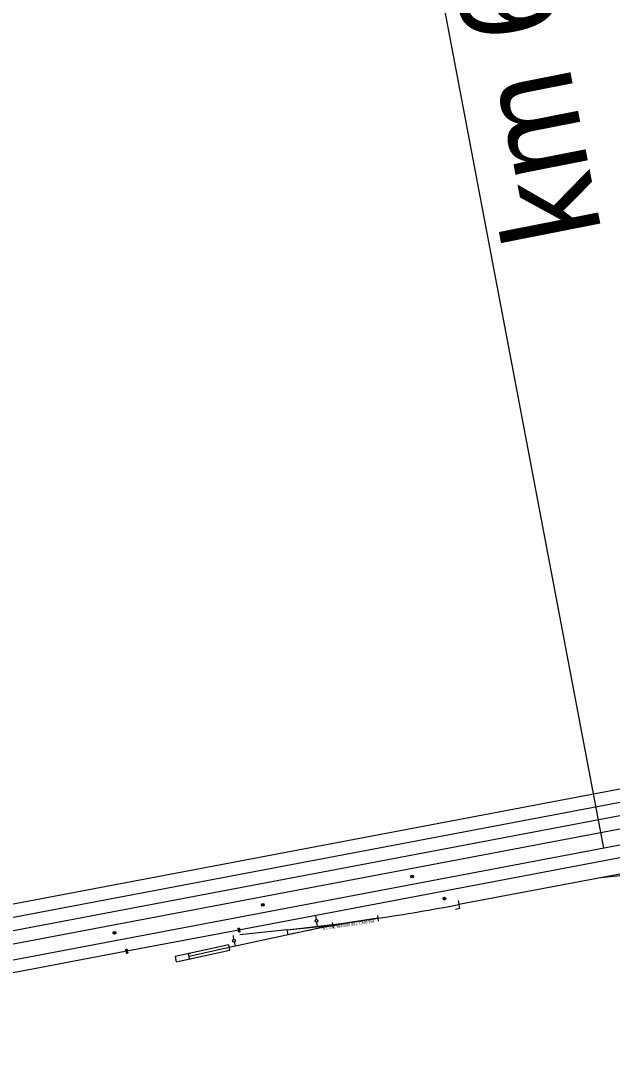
# Model space of a CAD drawing. Extents: x 6540402 to 6566579, y 5525343 to 5532423.
# Drawn here: x 6557411.7 to 6557627, y 5528631.9 to 5529013.3 of the extents above; entities that cross this region are included whole.
import ezdxf

# ---------------------------------------------------------------- set-up
doc = ezdxf.new("R2010")
doc.units = 0
for name, color, linetype in [('IR_ps_geometria', 7, 'Continuous'), ('T_plan_koziol oporowy', 7, 'Continuous'), ('TOR_PS_ODW-studnie betonowe', 7, 'Continuous'), ('TOR_PS_OPIS_T-opisy dodatkowe', 7, 'Continuous'), ('TOR_PS_OPIS_T-symbole geometrii', 7, 'Continuous'), ('TOR_PS_OPIS_T-ukresy', 7, 'Continuous'), ('TOR_PS_T-rozjazdy projektowane', 7, 'Continuous'), ('TOR_PS_T-tory projektowane', 7, 'Continuous')]:
    doc.layers.add(name, color=color, linetype=linetype)

# ---------------------------------------------------------------- blocks, each defined once
blk = doc.blocks.new('koziol 15+5')
at = {"layer": 'T_plan_koziol oporowy'}
for p, q in [((15, 1), (14.3, 1)), ((15, 1), (15, -1)), ((20, 0), (20, 1)), ((0, 0), (15, 0)), ((15, -1), (14.3, -1))]:
    blk.add_line(p, q, dxfattribs=at)
blk.add_lwpolyline([(20, 1), (0, 1), (0, -1), (20, -1)], close=True, dxfattribs=at)

msp = doc.modelspace()

# ---------------------------------------------------------------- linework, layer by layer
at = {"layer": 'IR_ps_geometria'}
for points in [[(6557491.12, 5528682.16), (6557491.16, 5528681.91), (6557491.2, 5528681.92), (6557491.23, 5528681.92), (6557491.26, 5528681.91), (6557491.29, 5528681.9), (6557491.32, 5528681.89), (6557491.35, 5528681.88), (6557491.38, 5528681.85), (6557491.4, 5528681.83), (6557491.42, 5528681.81), (6557491.44, 5528681.78), (6557491.45, 5528681.75), (6557491.46, 5528681.71), (6557491.46, 5528681.68), (6557491.46, 5528681.65), (6557491.46, 5528681.62), (6557491.45, 5528681.59), (6557491.43, 5528681.56), (6557491.42, 5528681.53), (6557491.4, 5528681.5), (6557491.37, 5528681.48), (6557491.35, 5528681.46), (6557491.32, 5528681.44), (6557491.29, 5528681.43), (6557491.26, 5528681.42), (6557491.22, 5528681.42), (6557491.19, 5528681.42), (6557491.16, 5528681.42), (6557491.13, 5528681.43), (6557491.1, 5528681.45), (6557491.07, 5528681.46), (6557491.04, 5528681.48), (6557491.02, 5528681.51), (6557491, 5528681.53), (6557490.99, 5528681.56), (6557490.97, 5528681.59), (6557490.96, 5528681.62), (6557490.96, 5528681.65), (6557490.96, 5528681.69), (6557490.97, 5528681.72), (6557490.97, 5528681.75), (6557490.99, 5528681.78), (6557491, 5528681.81), (6557491.02, 5528681.83), (6557491.05, 5528681.86), (6557491.07, 5528681.88), (6557491.1, 5528681.89), (6557491.13, 5528681.91), (6557491.16, 5528681.91), (6557491.07, 5528682.41), (6557491.04, 5528682.4), (6557491.01, 5528682.4), (6557490.97, 5528682.41), (6557490.94, 5528682.41), (6557490.91, 5528682.43), (6557490.88, 5528682.44), (6557490.86, 5528682.46), (6557490.83, 5528682.49), (6557490.81, 5528682.51), (6557490.8, 5528682.54), (6557490.79, 5528682.57), (6557490.78, 5528682.6), (6557490.77, 5528682.64), (6557490.77, 5528682.67), (6557490.78, 5528682.7), (6557490.79, 5528682.73), (6557490.8, 5528682.76), (6557490.82, 5528682.79), (6557490.84, 5528682.82), (6557490.86, 5528682.84), (6557490.89, 5528682.86), (6557490.92, 5528682.88), (6557490.95, 5528682.89), (6557490.98, 5528682.9), (6557491.01, 5528682.9), (6557491.04, 5528682.9), (6557491.08, 5528682.9), (6557491.11, 5528682.89), (6557491.14, 5528682.87), (6557491.16, 5528682.86), (6557491.19, 5528682.84), (6557491.21, 5528682.81), (6557491.23, 5528682.79), (6557491.25, 5528682.76), (6557491.26, 5528682.73), (6557491.27, 5528682.7), (6557491.27, 5528682.67), (6557491.27, 5528682.63), (6557491.27, 5528682.6), (6557491.26, 5528682.57), (6557491.25, 5528682.54), (6557491.23, 5528682.51), (6557491.21, 5528682.48), (6557491.19, 5528682.46), (6557491.16, 5528682.44), (6557491.13, 5528682.43), (6557491.1, 5528682.41), (6557491.07, 5528682.41)], [(6557491.12, 5528682.16), (6557491.16, 5528681.91), (6557491.2, 5528681.92), (6557491.23, 5528681.92), (6557491.26, 5528681.91), (6557491.29, 5528681.9), (6557491.32, 5528681.89), (6557491.35, 5528681.88), (6557491.38, 5528681.85), (6557491.4, 5528681.83), (6557491.42, 5528681.81), (6557491.44, 5528681.78), (6557491.45, 5528681.75), (6557491.46, 5528681.71), (6557491.46, 5528681.68), (6557491.46, 5528681.65), (6557491.46, 5528681.62), (6557491.45, 5528681.59), (6557491.43, 5528681.56), (6557491.42, 5528681.53), (6557491.4, 5528681.5), (6557491.37, 5528681.48), (6557491.35, 5528681.46), (6557491.32, 5528681.44), (6557491.29, 5528681.43), (6557491.26, 5528681.42), (6557491.22, 5528681.42), (6557491.19, 5528681.42), (6557491.16, 5528681.42), (6557491.13, 5528681.43), (6557491.1, 5528681.45), (6557491.07, 5528681.46), (6557491.04, 5528681.48), (6557491.02, 5528681.51), (6557491, 5528681.53), (6557490.99, 5528681.56), (6557490.97, 5528681.59), (6557490.96, 5528681.62), (6557490.96, 5528681.65), (6557490.96, 5528681.69), (6557490.97, 5528681.72), (6557490.97, 5528681.75), (6557490.99, 5528681.78), (6557491, 5528681.81), (6557491.02, 5528681.83), (6557491.05, 5528681.86), (6557491.07, 5528681.88), (6557491.1, 5528681.89), (6557491.13, 5528681.91), (6557491.16, 5528681.91), (6557491.07, 5528682.41), (6557491.04, 5528682.4), (6557491.01, 5528682.4), (6557490.97, 5528682.41), (6557490.94, 5528682.41), (6557490.91, 5528682.43), (6557490.88, 5528682.44), (6557490.86, 5528682.46), (6557490.83, 5528682.49), (6557490.81, 5528682.51), (6557490.8, 5528682.54), (6557490.79, 5528682.57), (6557490.78, 5528682.6), (6557490.77, 5528682.64), (6557490.77, 5528682.67), (6557490.78, 5528682.7), (6557490.79, 5528682.73), (6557490.8, 5528682.76), (6557490.82, 5528682.79), (6557490.84, 5528682.82), (6557490.86, 5528682.84), (6557490.89, 5528682.86), (6557490.92, 5528682.88), (6557490.95, 5528682.89), (6557490.98, 5528682.9), (6557491.01, 5528682.9), (6557491.04, 5528682.9), (6557491.08, 5528682.9), (6557491.11, 5528682.89), (6557491.14, 5528682.87), (6557491.16, 5528682.86), (6557491.19, 5528682.84), (6557491.21, 5528682.81), (6557491.23, 5528682.79), (6557491.25, 5528682.76), (6557491.26, 5528682.73), (6557491.27, 5528682.7), (6557491.27, 5528682.67), (6557491.27, 5528682.63), (6557491.27, 5528682.6), (6557491.26, 5528682.57), (6557491.25, 5528682.54), (6557491.23, 5528682.51), (6557491.21, 5528682.48), (6557491.19, 5528682.46), (6557491.16, 5528682.44), (6557491.13, 5528682.43), (6557491.1, 5528682.41), (6557491.07, 5528682.41)], [(6557491.12, 5528682.16), (6557491.16, 5528681.91), (6557491.2, 5528681.92), (6557491.23, 5528681.92), (6557491.26, 5528681.91), (6557491.29, 5528681.9), (6557491.32, 5528681.89), (6557491.35, 5528681.88), (6557491.38, 5528681.85), (6557491.4, 5528681.83), (6557491.42, 5528681.81), (6557491.44, 5528681.78), (6557491.45, 5528681.75), (6557491.46, 5528681.71), (6557491.46, 5528681.68), (6557491.46, 5528681.65), (6557491.46, 5528681.62), (6557491.45, 5528681.59), (6557491.43, 5528681.56), (6557491.42, 5528681.53), (6557491.4, 5528681.5), (6557491.37, 5528681.48), (6557491.35, 5528681.46), (6557491.32, 5528681.44), (6557491.29, 5528681.43), (6557491.26, 5528681.42), (6557491.22, 5528681.42), (6557491.19, 5528681.42), (6557491.16, 5528681.42), (6557491.13, 5528681.43), (6557491.1, 5528681.45), (6557491.07, 5528681.46), (6557491.04, 5528681.48), (6557491.02, 5528681.51), (6557491, 5528681.53), (6557490.99, 5528681.56), (6557490.97, 5528681.59), (6557490.96, 5528681.62), (6557490.96, 5528681.65), (6557490.96, 5528681.69), (6557490.97, 5528681.72), (6557490.97, 5528681.75), (6557490.99, 5528681.78), (6557491, 5528681.81), (6557491.02, 5528681.83), (6557491.05, 5528681.86), (6557491.07, 5528681.88), (6557491.1, 5528681.89), (6557491.13, 5528681.91), (6557491.16, 5528681.91), (6557491.07, 5528682.41), (6557491.04, 5528682.4), (6557491.01, 5528682.4), (6557490.97, 5528682.41), (6557490.94, 5528682.41), (6557490.91, 5528682.43), (6557490.88, 5528682.44), (6557490.86, 5528682.46), (6557490.83, 5528682.49), (6557490.81, 5528682.51), (6557490.8, 5528682.54), (6557490.79, 5528682.57), (6557490.78, 5528682.6), (6557490.77, 5528682.64), (6557490.77, 5528682.67), (6557490.78, 5528682.7), (6557490.79, 5528682.73), (6557490.8, 5528682.76), (6557490.82, 5528682.79), (6557490.84, 5528682.82), (6557490.86, 5528682.84), (6557490.89, 5528682.86), (6557490.92, 5528682.88), (6557490.95, 5528682.89), (6557490.98, 5528682.9), (6557491.01, 5528682.9), (6557491.04, 5528682.9), (6557491.08, 5528682.9), (6557491.11, 5528682.89), (6557491.14, 5528682.87), (6557491.16, 5528682.86), (6557491.19, 5528682.84), (6557491.21, 5528682.81), (6557491.23, 5528682.79), (6557491.25, 5528682.76), (6557491.26, 5528682.73), (6557491.27, 5528682.7), (6557491.27, 5528682.67), (6557491.27, 5528682.63), (6557491.27, 5528682.6), (6557491.26, 5528682.57), (6557491.25, 5528682.54), (6557491.23, 5528682.51), (6557491.21, 5528682.48), (6557491.19, 5528682.46), (6557491.16, 5528682.44), (6557491.13, 5528682.43), (6557491.1, 5528682.41), (6557491.07, 5528682.41)], [(6557491.12, 5528682.16), (6557491.16, 5528681.91), (6557491.2, 5528681.92), (6557491.23, 5528681.92), (6557491.26, 5528681.91), (6557491.29, 5528681.9), (6557491.32, 5528681.89), (6557491.35, 5528681.88), (6557491.38, 5528681.85), (6557491.4, 5528681.83), (6557491.42, 5528681.81), (6557491.44, 5528681.78), (6557491.45, 5528681.75), (6557491.46, 5528681.71), (6557491.46, 5528681.68), (6557491.46, 5528681.65), (6557491.46, 5528681.62), (6557491.45, 5528681.59), (6557491.43, 5528681.56), (6557491.42, 5528681.53), (6557491.4, 5528681.5), (6557491.37, 5528681.48), (6557491.35, 5528681.46), (6557491.32, 5528681.44), (6557491.29, 5528681.43), (6557491.26, 5528681.42), (6557491.22, 5528681.42), (6557491.19, 5528681.42), (6557491.16, 5528681.42), (6557491.13, 5528681.43), (6557491.1, 5528681.45), (6557491.07, 5528681.46), (6557491.04, 5528681.48), (6557491.02, 5528681.51), (6557491, 5528681.53), (6557490.99, 5528681.56), (6557490.97, 5528681.59), (6557490.96, 5528681.62), (6557490.96, 5528681.65), (6557490.96, 5528681.69), (6557490.97, 5528681.72), (6557490.97, 5528681.75), (6557490.99, 5528681.78), (6557491, 5528681.81), (6557491.02, 5528681.83), (6557491.05, 5528681.86), (6557491.07, 5528681.88), (6557491.1, 5528681.89), (6557491.13, 5528681.91), (6557491.16, 5528681.91), (6557491.07, 5528682.41), (6557491.04, 5528682.4), (6557491.01, 5528682.4), (6557490.97, 5528682.41), (6557490.94, 5528682.41), (6557490.91, 5528682.43), (6557490.88, 5528682.44), (6557490.86, 5528682.46), (6557490.83, 5528682.49), (6557490.81, 5528682.51), (6557490.8, 5528682.54), (6557490.79, 5528682.57), (6557490.78, 5528682.6), (6557490.77, 5528682.64), (6557490.77, 5528682.67), (6557490.78, 5528682.7), (6557490.79, 5528682.73), (6557490.8, 5528682.76), (6557490.82, 5528682.79), (6557490.84, 5528682.82), (6557490.86, 5528682.84), (6557490.89, 5528682.86), (6557490.92, 5528682.88), (6557490.95, 5528682.89), (6557490.98, 5528682.9), (6557491.01, 5528682.9), (6557491.04, 5528682.9), (6557491.08, 5528682.9), (6557491.11, 5528682.89), (6557491.14, 5528682.87), (6557491.16, 5528682.86), (6557491.19, 5528682.84), (6557491.21, 5528682.81), (6557491.23, 5528682.79), (6557491.25, 5528682.76), (6557491.26, 5528682.73), (6557491.27, 5528682.7), (6557491.27, 5528682.67), (6557491.27, 5528682.63), (6557491.27, 5528682.6), (6557491.26, 5528682.57), (6557491.25, 5528682.54), (6557491.23, 5528682.51), (6557491.21, 5528682.48), (6557491.19, 5528682.46), (6557491.16, 5528682.44), (6557491.13, 5528682.43), (6557491.1, 5528682.41), (6557491.07, 5528682.41)], [(6557450.25, 5528674.41), (6557450.3, 5528674.17), (6557450.33, 5528674.17), (6557450.36, 5528674.17), (6557450.39, 5528674.17), (6557450.43, 5528674.16), (6557450.46, 5528674.15), (6557450.48, 5528674.13), (6557450.51, 5528674.11), (6557450.53, 5528674.09), (6557450.55, 5528674.06), (6557450.57, 5528674.03), (6557450.58, 5528674), (6557450.59, 5528673.97), (6557450.59, 5528673.94), (6557450.59, 5528673.9), (6557450.59, 5528673.87), (6557450.58, 5528673.84), (6557450.57, 5528673.81), (6557450.55, 5528673.78), (6557450.53, 5528673.76), (6557450.51, 5528673.73), (6557450.48, 5528673.71), (6557450.45, 5528673.7), (6557450.42, 5528673.68), (6557450.39, 5528673.68), (6557450.36, 5528673.67), (6557450.32, 5528673.67), (6557450.29, 5528673.68), (6557450.26, 5528673.69), (6557450.23, 5528673.7), (6557450.2, 5528673.72), (6557450.18, 5528673.74), (6557450.15, 5528673.76), (6557450.13, 5528673.78), (6557450.12, 5528673.81), (6557450.11, 5528673.84), (6557450.1, 5528673.88), (6557450.09, 5528673.91), (6557450.09, 5528673.94), (6557450.1, 5528673.97), (6557450.11, 5528674), (6557450.12, 5528674.03), (6557450.14, 5528674.06), (6557450.16, 5528674.09), (6557450.18, 5528674.11), (6557450.21, 5528674.13), (6557450.23, 5528674.15), (6557450.27, 5528674.16), (6557450.3, 5528674.17), (6557450.2, 5528674.66), (6557450.17, 5528674.65), (6557450.14, 5528674.66), (6557450.11, 5528674.66), (6557450.07, 5528674.67), (6557450.04, 5528674.68), (6557450.02, 5528674.7), (6557449.99, 5528674.72), (6557449.97, 5528674.74), (6557449.95, 5528674.77), (6557449.93, 5528674.8), (6557449.92, 5528674.83), (6557449.91, 5528674.86), (6557449.91, 5528674.89), (6557449.91, 5528674.92), (6557449.91, 5528674.96), (6557449.92, 5528674.99), (6557449.93, 5528675.02), (6557449.95, 5528675.05), (6557449.97, 5528675.07), (6557449.99, 5528675.09), (6557450.02, 5528675.11), (6557450.05, 5528675.13), (6557450.08, 5528675.14), (6557450.11, 5528675.15), (6557450.14, 5528675.15), (6557450.18, 5528675.15), (6557450.21, 5528675.15), (6557450.24, 5528675.14), (6557450.27, 5528675.13), (6557450.3, 5528675.11), (6557450.32, 5528675.09), (6557450.35, 5528675.07), (6557450.37, 5528675.04), (6557450.38, 5528675.01), (6557450.39, 5528674.98), (6557450.4, 5528674.95), (6557450.41, 5528674.92), (6557450.41, 5528674.89), (6557450.4, 5528674.85), (6557450.39, 5528674.82), (6557450.38, 5528674.79), (6557450.36, 5528674.76), (6557450.34, 5528674.74), (6557450.32, 5528674.72), (6557450.29, 5528674.7), (6557450.27, 5528674.68), (6557450.24, 5528674.67), (6557450.2, 5528674.66)], [(6557450.25, 5528674.41), (6557450.3, 5528674.17), (6557450.33, 5528674.17), (6557450.36, 5528674.17), (6557450.39, 5528674.17), (6557450.43, 5528674.16), (6557450.46, 5528674.15), (6557450.48, 5528674.13), (6557450.51, 5528674.11), (6557450.53, 5528674.09), (6557450.55, 5528674.06), (6557450.57, 5528674.03), (6557450.58, 5528674), (6557450.59, 5528673.97), (6557450.59, 5528673.94), (6557450.59, 5528673.9), (6557450.59, 5528673.87), (6557450.58, 5528673.84), (6557450.57, 5528673.81), (6557450.55, 5528673.78), (6557450.53, 5528673.76), (6557450.51, 5528673.73), (6557450.48, 5528673.71), (6557450.45, 5528673.7), (6557450.42, 5528673.68), (6557450.39, 5528673.68), (6557450.36, 5528673.67), (6557450.32, 5528673.67), (6557450.29, 5528673.68), (6557450.26, 5528673.69), (6557450.23, 5528673.7), (6557450.2, 5528673.72), (6557450.18, 5528673.74), (6557450.15, 5528673.76), (6557450.13, 5528673.78), (6557450.12, 5528673.81), (6557450.11, 5528673.84), (6557450.1, 5528673.88), (6557450.09, 5528673.91), (6557450.09, 5528673.94), (6557450.1, 5528673.97), (6557450.11, 5528674), (6557450.12, 5528674.03), (6557450.14, 5528674.06), (6557450.16, 5528674.09), (6557450.18, 5528674.11), (6557450.21, 5528674.13), (6557450.23, 5528674.15), (6557450.27, 5528674.16), (6557450.3, 5528674.17), (6557450.2, 5528674.66), (6557450.17, 5528674.65), (6557450.14, 5528674.66), (6557450.11, 5528674.66), (6557450.07, 5528674.67), (6557450.04, 5528674.68), (6557450.02, 5528674.7), (6557449.99, 5528674.72), (6557449.97, 5528674.74), (6557449.95, 5528674.77), (6557449.93, 5528674.8), (6557449.92, 5528674.83), (6557449.91, 5528674.86), (6557449.91, 5528674.89), (6557449.91, 5528674.92), (6557449.91, 5528674.96), (6557449.92, 5528674.99), (6557449.93, 5528675.02), (6557449.95, 5528675.05), (6557449.97, 5528675.07), (6557449.99, 5528675.09), (6557450.02, 5528675.11), (6557450.05, 5528675.13), (6557450.08, 5528675.14), (6557450.11, 5528675.15), (6557450.14, 5528675.15), (6557450.18, 5528675.15), (6557450.21, 5528675.15), (6557450.24, 5528675.14), (6557450.27, 5528675.13), (6557450.3, 5528675.11), (6557450.32, 5528675.09), (6557450.35, 5528675.07), (6557450.37, 5528675.04), (6557450.38, 5528675.01), (6557450.39, 5528674.98), (6557450.4, 5528674.95), (6557450.41, 5528674.92), (6557450.41, 5528674.89), (6557450.4, 5528674.85), (6557450.39, 5528674.82), (6557450.38, 5528674.79), (6557450.36, 5528674.76), (6557450.34, 5528674.74), (6557450.32, 5528674.72), (6557450.29, 5528674.7), (6557450.27, 5528674.68), (6557450.24, 5528674.67), (6557450.2, 5528674.66)], [(6557450.25, 5528674.41), (6557450.3, 5528674.17), (6557450.33, 5528674.17), (6557450.36, 5528674.17), (6557450.39, 5528674.17), (6557450.43, 5528674.16), (6557450.46, 5528674.15), (6557450.48, 5528674.13), (6557450.51, 5528674.11), (6557450.53, 5528674.09), (6557450.55, 5528674.06), (6557450.57, 5528674.03), (6557450.58, 5528674), (6557450.59, 5528673.97), (6557450.59, 5528673.94), (6557450.59, 5528673.9), (6557450.59, 5528673.87), (6557450.58, 5528673.84), (6557450.57, 5528673.81), (6557450.55, 5528673.78), (6557450.53, 5528673.76), (6557450.51, 5528673.73), (6557450.48, 5528673.71), (6557450.45, 5528673.7), (6557450.42, 5528673.68), (6557450.39, 5528673.68), (6557450.36, 5528673.67), (6557450.32, 5528673.67), (6557450.29, 5528673.68), (6557450.26, 5528673.69), (6557450.23, 5528673.7), (6557450.2, 5528673.72), (6557450.18, 5528673.74), (6557450.15, 5528673.76), (6557450.13, 5528673.78), (6557450.12, 5528673.81), (6557450.11, 5528673.84), (6557450.1, 5528673.88), (6557450.09, 5528673.91), (6557450.09, 5528673.94), (6557450.1, 5528673.97), (6557450.11, 5528674), (6557450.12, 5528674.03), (6557450.14, 5528674.06), (6557450.16, 5528674.09), (6557450.18, 5528674.11), (6557450.21, 5528674.13), (6557450.23, 5528674.15), (6557450.27, 5528674.16), (6557450.3, 5528674.17), (6557450.2, 5528674.66), (6557450.17, 5528674.65), (6557450.14, 5528674.66), (6557450.11, 5528674.66), (6557450.07, 5528674.67), (6557450.04, 5528674.68), (6557450.02, 5528674.7), (6557449.99, 5528674.72), (6557449.97, 5528674.74), (6557449.95, 5528674.77), (6557449.93, 5528674.8), (6557449.92, 5528674.83), (6557449.91, 5528674.86), (6557449.91, 5528674.89), (6557449.91, 5528674.92), (6557449.91, 5528674.96), (6557449.92, 5528674.99), (6557449.93, 5528675.02), (6557449.95, 5528675.05), (6557449.97, 5528675.07), (6557449.99, 5528675.09), (6557450.02, 5528675.11), (6557450.05, 5528675.13), (6557450.08, 5528675.14), (6557450.11, 5528675.15), (6557450.14, 5528675.15), (6557450.18, 5528675.15), (6557450.21, 5528675.15), (6557450.24, 5528675.14), (6557450.27, 5528675.13), (6557450.3, 5528675.11), (6557450.32, 5528675.09), (6557450.35, 5528675.07), (6557450.37, 5528675.04), (6557450.38, 5528675.01), (6557450.39, 5528674.98), (6557450.4, 5528674.95), (6557450.41, 5528674.92), (6557450.41, 5528674.89), (6557450.4, 5528674.85), (6557450.39, 5528674.82), (6557450.38, 5528674.79), (6557450.36, 5528674.76), (6557450.34, 5528674.74), (6557450.32, 5528674.72), (6557450.29, 5528674.7), (6557450.27, 5528674.68), (6557450.24, 5528674.67), (6557450.2, 5528674.66)], [(6557450.25, 5528674.41), (6557450.3, 5528674.17), (6557450.33, 5528674.17), (6557450.36, 5528674.17), (6557450.39, 5528674.17), (6557450.43, 5528674.16), (6557450.46, 5528674.15), (6557450.48, 5528674.13), (6557450.51, 5528674.11), (6557450.53, 5528674.09), (6557450.55, 5528674.06), (6557450.57, 5528674.03), (6557450.58, 5528674), (6557450.59, 5528673.97), (6557450.59, 5528673.94), (6557450.59, 5528673.9), (6557450.59, 5528673.87), (6557450.58, 5528673.84), (6557450.57, 5528673.81), (6557450.55, 5528673.78), (6557450.53, 5528673.76), (6557450.51, 5528673.73), (6557450.48, 5528673.71), (6557450.45, 5528673.7), (6557450.42, 5528673.68), (6557450.39, 5528673.68), (6557450.36, 5528673.67), (6557450.32, 5528673.67), (6557450.29, 5528673.68), (6557450.26, 5528673.69), (6557450.23, 5528673.7), (6557450.2, 5528673.72), (6557450.18, 5528673.74), (6557450.15, 5528673.76), (6557450.13, 5528673.78), (6557450.12, 5528673.81), (6557450.11, 5528673.84), (6557450.1, 5528673.88), (6557450.09, 5528673.91), (6557450.09, 5528673.94), (6557450.1, 5528673.97), (6557450.11, 5528674), (6557450.12, 5528674.03), (6557450.14, 5528674.06), (6557450.16, 5528674.09), (6557450.18, 5528674.11), (6557450.21, 5528674.13), (6557450.23, 5528674.15), (6557450.27, 5528674.16), (6557450.3, 5528674.17), (6557450.2, 5528674.66), (6557450.17, 5528674.65), (6557450.14, 5528674.66), (6557450.11, 5528674.66), (6557450.07, 5528674.67), (6557450.04, 5528674.68), (6557450.02, 5528674.7), (6557449.99, 5528674.72), (6557449.97, 5528674.74), (6557449.95, 5528674.77), (6557449.93, 5528674.8), (6557449.92, 5528674.83), (6557449.91, 5528674.86), (6557449.91, 5528674.89), (6557449.91, 5528674.92), (6557449.91, 5528674.96), (6557449.92, 5528674.99), (6557449.93, 5528675.02), (6557449.95, 5528675.05), (6557449.97, 5528675.07), (6557449.99, 5528675.09), (6557450.02, 5528675.11), (6557450.05, 5528675.13), (6557450.08, 5528675.14), (6557450.11, 5528675.15), (6557450.14, 5528675.15), (6557450.18, 5528675.15), (6557450.21, 5528675.15), (6557450.24, 5528675.14), (6557450.27, 5528675.13), (6557450.3, 5528675.11), (6557450.32, 5528675.09), (6557450.35, 5528675.07), (6557450.37, 5528675.04), (6557450.38, 5528675.01), (6557450.39, 5528674.98), (6557450.4, 5528674.95), (6557450.41, 5528674.92), (6557450.41, 5528674.89), (6557450.4, 5528674.85), (6557450.39, 5528674.82), (6557450.38, 5528674.79), (6557450.36, 5528674.76), (6557450.34, 5528674.74), (6557450.32, 5528674.72), (6557450.29, 5528674.7), (6557450.27, 5528674.68), (6557450.24, 5528674.67), (6557450.2, 5528674.66)]]:
    msp.add_lwpolyline(points, close=True, dxfattribs=at)
at = {"layer": 'TOR_PS_ODW-studnie betonowe'}
for centre, radius in [((6557554.22, 5528701.65), 0.5), ((6557554.22, 5528701.65), 0.25), ((6557565.93, 5528693.59), 0.5), ((6557565.93, 5528693.59), 0.25), ((6557499.84, 5528691.34), 0.5), ((6557499.84, 5528691.34), 0.25), ((6557445.8, 5528681.1), 0.5), ((6557445.8, 5528681.1), 0.25)]:
    msp.add_circle(centre, radius, dxfattribs=at)
at = {"layer": 'TOR_PS_OPIS_T-opisy dodatkowe'}
msp.add_line((6557624.06, 5528711.94), (6557480.69, 5529468.32), dxfattribs=at)
at = {"layer": 'TOR_PS_OPIS_T-symbole geometrii'}
for p, q in [((6557570.93, 5528692.91), (6557571.48, 5528689.96)), ((6557571.48, 5528689.96), (6557570.01, 5528689.68))]:
    msp.add_line(p, q, dxfattribs=at)
at = {"layer": 'TOR_PS_OPIS_T-ukresy'}
for p, q in [((6557518.97, 5528687.44), (6557519.25, 5528685.97)), ((6557519.41, 5528684.98), (6557519.58, 5528683.48)), ((6557519.85, 5528685.48), (6557519.85, 5528685.48)), ((6557489.25, 5528678.7), (6557489.09, 5528680.21)), ((6557489.42, 5528677.72), (6557489.74, 5528676.24))]:
    msp.add_line(p, q, dxfattribs=at)
for centre in [(6557519.35, 5528685.48), (6557489.31, 5528678.21)]:
    msp.add_circle(centre, 0.5, dxfattribs=at)
at = {"layer": 'TOR_PS_T-rozjazdy projektowane'}
for p, q in [((6557525.1, 5528684.89), (6557525.4, 5528682.91)), ((6557541.52, 5528687.43), (6557541.82, 5528685.45))]:
    msp.add_line(p, q, dxfattribs=at)
msp.add_lwpolyline([(6557508.71, 5528682.26), (6557525.25, 5528683.9), (6557541.67, 5528686.44), (6557525.25, 5528683.9), (6557509, 5528680.45)], close=True, dxfattribs=at)
at = {"layer": 'TOR_PS_T-tory projektowane'}
for p, q in [((6558571.55, 5528891.54), (6557352.88, 5528660.54)), ((6557651.07, 5528737.47), (6557379.51, 5528685.99)), ((6557652.06, 5528732.82), (6557269.96, 5528660.39)), ((6557664.82, 5528730.4), (6555967.41, 5528408.66)), ((6557665.78, 5528725.75), (6557203.03, 5528638.04)), ((6557721.75, 5528719.97), (6557571.21, 5528691.44)), ((6557657.08, 5528713.62), (6557491.12, 5528682.16)), ((6557653.73, 5528704.37), (6557621.87, 5528701.04)), ((6557491.12, 5528682.16), (6557450.25, 5528674.41)), ((6557508.71, 5528682.26), (6557491.37, 5528680.45)), ((6557508.99, 5528680.45), (6557487.59, 5528675.78)), ((6557450.25, 5528674.41), (6556612.98, 5528515.71))]:
    msp.add_line(p, q, dxfattribs=at)
for centre, radius, start, end in [((6557429.67, 5529438.14), 760, 278.47478, 280.73324), ((6557429.67, 5529438.14), 760, 275.9696, 278.47478), ((6557614.8, 5528195.61), 496.25, 98.4748, 102.3114)]:
    msp.add_arc(centre, radius, start, end, dxfattribs=at)

# ---------------------------------------------------------------- block references
at = {"layer": 'T_plan_koziol oporowy', "rotation": -167.68858310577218}
msp.add_blockref('koziol 15+5', (6557487.59, 5528675.78), dxfattribs=at)

# ---------------------------------------------------------------- texts
at = {"layer": 'TOR_PS_OPIS_T-opisy dodatkowe'}
msp.add_text('km 61+472(istn.)=km 61+472(proj.)  ', height=35, rotation=101.1578, dxfattribs=at).set_placement((6557623.34, 5528936.43))
at = {"layer": 'TOR_PS_T-rozjazdy projektowane'}
msp.add_text('Rłd-60E1-760,000/496,252-1:9', height=1, rotation=188.7993, dxfattribs=at).set_placement((6557540.31, 5528685.97))

doc.saveas('drawing.dxf')
